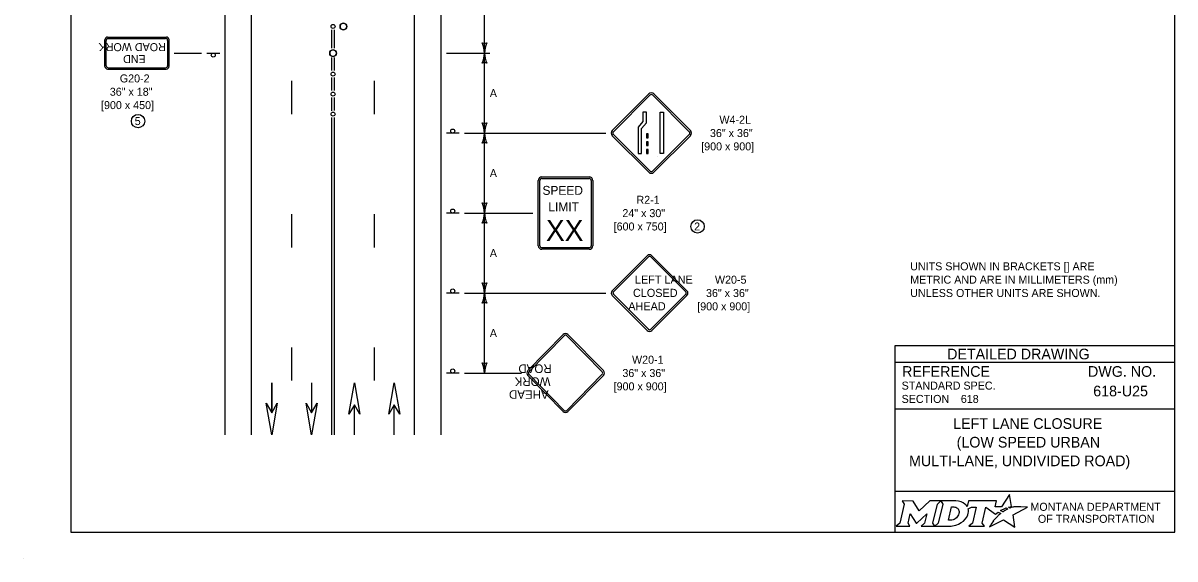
# Model space of a CAD drawing. Extents: x 49991.4 to 50021, y 49987.6 to 50011.4.
# Drawn here: x 49999.98 to 50008.61, y 49999.86 to 50003.88 of the extents above; entities that cross this region are included whole.
import ezdxf

# ---------------------------------------------------------------- set-up
doc = ezdxf.new("R2010")
doc.units = 0
for name, color, linetype in [('Level 1', 7, 'Continuous'), ('Level 2', 7, 'Continuous'), ('Level 25', 7, 'Continuous'), ('Level 3', 7, 'Continuous'), ('S_BOT_RW_TTL_Sheet_No_DF', 7, 'Continuous')]:
    doc.layers.add(name, color=color, linetype=linetype)

msp = doc.modelspace()

# ---------------------------------------------------------------- linework, layer by layer
at = {"layer": 'Level 1'}
for p, q in [((50001.4911, 50000.794), (50001.4911, 50008.6221)), ((50001.691, 50000.794), (50001.691, 50008.6221)), ((50002.911, 50000.794), (50002.911, 50008.6221)), ((50003.1109, 50000.794), (50003.1109, 50008.6221)), ((50002.291, 50003.6933), (50002.291, 50003.8311)), ((50002.311, 50003.6933), (50002.311, 50003.8311)), ((50000.5911, 50003.5573), (50000.5911, 50003.7573)), ((50000.6011, 50003.5623), (50000.6011, 50003.7523)), ((50000.6112, 50003.7773), (50001.0512, 50003.7773)), ((50000.6161, 50003.7673), (50001.0461, 50003.7673)), ((50001.0611, 50003.7523), (50001.0611, 50003.5623)), ((50001.0711, 50003.7573), (50001.0711, 50003.5573)), ((50001.3551, 50003.6573), (50001.4511, 50003.6573)), ((50002.291, 50003.5256), (50002.291, 50003.6233)), ((50002.311, 50003.5257), (50002.311, 50003.6233)), ((50000.6111, 50003.5373), (50001.0511, 50003.5373)), ((50000.6161, 50003.5473), (50001.0461, 50003.5473)), ((50001.9911, 50003.2), (50001.9911, 50003.45)), ((50002.291, 50003.3755), (50002.291, 50003.4732)), ((50002.311, 50003.3756), (50002.311, 50003.4732)), ((50002.6111, 50003.2), (50002.6111, 50003.45)), ((50002.291, 50003.2254), (50002.291, 50003.3231)), ((50002.311, 50003.2256), (50002.311, 50003.3231)), ((50002.291, 50000.794), (50002.291, 50003.1731)), ((50002.311, 50000.794), (50002.311, 50003.1731)), ((50003.2469, 50003.0573), (50003.1509, 50003.0573)), ((50003.8676, 50002.7292), (50004.2221, 50002.7292)), ((50003.8676, 50002.7168), (50004.2221, 50002.7168)), ((50003.8404, 50002.2125), (50003.8404, 50002.7021)), ((50003.8528, 50002.2125), (50003.8528, 50002.7021)), ((50004.2369, 50002.7021), (50004.2369, 50002.2125)), ((50004.2493, 50002.7021), (50004.2493, 50002.2125)), ((50001.9911, 50002.2), (50001.9911, 50002.45)), ((50002.6111, 50002.2), (50002.6111, 50002.45)), ((50003.2469, 50002.4573), (50003.1509, 50002.4573)), ((50004.2221, 50002.1977), (50003.8676, 50002.1977)), ((50004.2221, 50002.1853), (50003.8676, 50002.1853)), ((50004.6572, 50002.1376), (50004.3946, 50001.875)), ((50004.666, 50002.1289), (50004.4034, 50001.8662)), ((50004.9464, 50001.8662), (50004.6837, 50002.1289)), ((50004.9551, 50001.875), (50004.6926, 50002.1376)), ((50003.2469, 50001.8573), (50003.1509, 50001.8573)), ((50004.4034, 50001.8485), (50004.666, 50001.5858)), ((50004.6749, 50001.8573), (50004.6749, 50001.8573)), ((50004.6749, 50001.8573), (50004.6749, 50001.8573)), ((50004.6749, 50001.8573), (50004.6749, 50001.8573)), ((50004.6837, 50001.5858), (50004.9464, 50001.8485)), ((50004.3946, 50001.8397), (50004.6572, 50001.5771)), ((50004.6926, 50001.5771), (50004.9551, 50001.8397)), ((50003.7615, 50001.2754), (50004.0267, 50001.5461)), ((50003.7704, 50001.2667), (50004.0356, 50001.5374)), ((50004.0542, 50001.5374), (50004.3193, 50001.2667)), ((50004.063, 50001.5461), (50004.3282, 50001.2754)), ((50001.9911, 50001.2), (50001.9911, 50001.45)), ((50002.6111, 50001.2), (50002.6111, 50001.45)), ((50003.2469, 50001.2572), (50003.1509, 50001.2572)), ((50004.0267, 50000.9685), (50003.7615, 50001.2392)), ((50004.0356, 50000.9772), (50003.7704, 50001.2479)), ((50004.3193, 50001.2479), (50004.0542, 50000.9772)), ((50004.3282, 50001.2392), (50004.063, 50000.9685)), ((50001.8409, 50001.1841), (50001.8409, 50000.9582)), ((50001.8413, 50001.1841), (50001.8413, 50000.9582)), ((50002.1403, 50001.1841), (50002.1403, 50000.9582)), ((50002.1407, 50001.1841), (50002.1407, 50000.9582)), ((50002.4611, 50000.794), (50002.4611, 50001.0199)), ((50002.4613, 50000.794), (50002.4613, 50001.0199)), ((50002.7605, 50000.7939), (50002.7605, 50001.0198)), ((50002.7607, 50000.7939), (50002.7607, 50001.0198)), ((49999.9766, 49999.8624), (49999.9766, 49999.8624))]:
    msp.add_line(p, q, dxfattribs=at)
for points in [[(50008.6146, 50011.2628), (50000.3356, 50011.2628), (50000.3356, 50000.0624), (50008.6146, 50000.0624)], [(50002.4193, 50000.9476), (50002.4611, 50001.1841), (50002.5029, 50000.9476), (50002.4611, 50001.0198)], [(50002.7187, 50000.9475), (50002.7605, 50001.184), (50002.8023, 50000.9475), (50002.7605, 50001.0197)], [(50001.8829, 50001.0305), (50001.8413, 50000.794), (50001.7993, 50001.0305), (50001.8413, 50000.9583)], [(50002.1823, 50001.0305), (50002.1407, 50000.794), (50002.0987, 50001.0305), (50002.1407, 50000.9583)]]:
    msp.add_lwpolyline(points, close=True, dxfattribs=at)
for centre, radius in [((50002.301, 50003.8573), 0.015), ((50002.3785, 50003.8573), 0.025), ((50001.4031, 50003.6421), 0.0152), ((50002.301, 50003.6573), 0.025), ((50002.301, 50003.4994), 0.015), ((50002.301, 50003.3493), 0.015), ((50002.301, 50003.1993), 0.015), ((50003.1989, 50003.0725), 0.0152), ((50003.1989, 50002.4725), 0.0152), ((50003.1989, 50001.8725), 0.0152), ((50003.1989, 50001.2725), 0.0152)]:
    msp.add_circle(centre, radius, dxfattribs=at)
for centre, radius, start, end in [((50002.3785, 50003.8573), 0.025, 360, 180), ((50002.3785, 50003.8573), 0.025, 180, 0), ((50000.6112, 50003.7573), 0.02, 90, 180), ((50000.6161, 50003.7523), 0.015, 90, 180), ((50001.0461, 50003.7523), 0.015, 360, 90), ((50001.0512, 50003.7573), 0.02, 360, 90), ((50002.301, 50003.6573), 0.025, 360, 180), ((50002.301, 50003.6573), 0.025, 180, 0), ((50000.6111, 50003.5573), 0.02, 180, 270), ((50000.6161, 50003.5623), 0.015, 180, 270), ((50001.0461, 50003.5623), 0.015, 270, 360), ((50001.0511, 50003.5573), 0.02, 270, 360), ((50003.8676, 50002.7021), 0.0272, 90, 180), ((50003.8676, 50002.7021), 0.0148, 90, 180), ((50004.2221, 50002.7021), 0.0272, 0, 90), ((50004.2221, 50002.7021), 0.0148, 0, 90), ((50003.8676, 50002.2125), 0.0272, 180, 270), ((50003.8676, 50002.2125), 0.0148, 180, 270), ((50004.2221, 50002.2125), 0.0148, 270, 360), ((50004.2221, 50002.2125), 0.0272, 270, 360), ((50004.6749, 50002.1199), 0.025, 45, 135), ((50004.6749, 50002.12), 0.0125, 45.00005, 135.00016), ((50004.4123, 50001.8573), 0.025, 135, 225), ((50004.4122, 50001.8573), 0.0125, 135.00016, 224.99995), ((50004.9376, 50001.8573), 0.0125, 314.99984, 45.00005), ((50004.9375, 50001.8573), 0.025, 315, 45), ((50004.6749, 50001.5947), 0.0125, 224.99995, 314.99984), ((50004.6749, 50001.5947), 0.025, 225, 315)]:
    msp.add_arc(centre, radius, start, end, dxfattribs=at)
for centre, major_axis, ratio, start_param, end_param in [((50004.0449, 50001.5279), (0, 0.0258), 0.98963, 5.497787, 7.068583), ((50004.0449, 50001.5279), (0, 0.0134), 0.98, 5.497787, 7.068583), ((50003.7796, 50001.2572), (0, 0.0258), 0.98963, 0.785394, 2.356194), ((50003.7796, 50001.2572), (0, 0.0134), 0.98, 0.785394, 2.356194), ((50004.3101, 50001.2572), (0, 0.0134), 0.98, 3.926991, 5.497787), ((50004.3101, 50001.2572), (0, 0.0258), 0.98963, 3.926991, 5.497787), ((50004.0449, 50000.9866), (0, -0.0134), 0.98, 5.497795, 7.068583), ((50004.0449, 50000.9866), (0, -0.0258), 0.98963, 5.497795, 7.068583)]:
    msp.add_ellipse(centre, major_axis=major_axis, ratio=ratio, start_param=start_param, end_param=end_param, dxfattribs=at)
at = {"layer": 'Level 2'}
for p, q in [((50008.6146, 50001.4624), (50006.5146, 50001.4624)), ((50006.5146, 50001.4624), (50006.5146, 50000.0624)), ((50008.6146, 50001.3374), (50006.5146, 50001.3374)), ((50008.2507, 50001.1223), (50008.2507, 50001.1223)), ((50008.6146, 50000.9874), (50006.5146, 50000.9874)), ((50007.0089, 50001.0629), (50007.0089, 50001.0629)), ((50007.5646, 50000.7383), (50007.5646, 50000.7383)), ((50008.6146, 50000.3693), (50006.5146, 50000.3693))]:
    msp.add_line(p, q, dxfattribs=at)
for points in [[(50006.5701, 50000.2974), (50006.5842, 50000.274), (50006.5507, 50000.1307), (50006.525, 50000.1082), (50006.6266, 50000.1082), (50006.6131, 50000.131), (50006.6293, 50000.2011), (50006.673, 50000.1321), (50006.6783, 50000.1321), (50006.7534, 50000.2016), (50006.737, 50000.1305), (50006.7123, 50000.1085), (50006.8139, 50000.1085), (50006.8001, 50000.1318), (50006.8333, 50000.2742)], [(50006.8333, 50000.2742), (50006.8586, 50000.2974), (50006.7762, 50000.2974), (50006.6966, 50000.2244), (50006.6521, 50000.2971), (50006.5701, 50000.2974)], [(50006.9722, 50000.2974), (50006.8586, 50000.2974), (50006.8733, 50000.2745), (50006.8394, 50000.1307), (50006.8139, 50000.1085), (50006.9245, 50000.1085)], [(50007.3771, 50000.2447), (50007.3668, 50000.2503), (50007.3784, 50000.2531), (50007.39, 50000.2551), (50007.3726, 50000.3452), (50007.3131, 50000.2539), (50007.2658, 50000.2532), (50007.2761, 50000.2973), (50007.0669, 50000.2974), (50007.0568, 50000.2549), (50007.051, 50000.2632)], [(50006.9962, 50000.2107), (50006.995, 50000.2026), (50006.9918, 50000.1933), (50006.9876, 50000.1851), (50006.982, 50000.1776), (50006.9755, 50000.1707), (50006.9676, 50000.1644), (50006.9593, 50000.1597), (50006.9502, 50000.1558), (50006.9411, 50000.1535), (50006.9319, 50000.1526), (50006.916, 50000.1526), (50006.9396, 50000.2526), (50006.9556, 50000.2526), (50006.9632, 50000.252), (50006.9708, 50000.2501), (50006.9774, 50000.2471), (50006.9835, 50000.2429), (50006.9883, 50000.2379), (50006.992, 50000.2319), (50006.9947, 50000.2257), (50006.9963, 50000.2183), (50006.9963, 50000.2153), (50006.9962, 50000.2107)], [(50007.0636, 50000.2383), (50007.0882, 50000.2514), (50007.1251, 50000.2514), (50007.0965, 50000.1309), (50007.069, 50000.1082), (50007.1852, 50000.1082), (50007.1682, 50000.1311), (50007.1964, 50000.2513), (50007.2677, 50000.1996), (50007.2888, 50000.2147), (50007.3085, 50000.2038)], [(50007.2527, 50000.1479), (50007.2374, 50000.1235), (50007.2327, 50000.116), (50007.2269, 50000.1074), (50007.2246, 50000.1031), (50007.3299, 50000.1562), (50007.4138, 50000.1011), (50007.4007, 50000.1938), (50007.5076, 50000.2522), (50007.4583, 50000.253), (50007.4282, 50000.2534), (50007.4074, 50000.2537), (50007.4006, 50000.2522), (50007.3957, 50000.251), (50007.3873, 50000.2487), (50007.3771, 50000.2447)], [(50007.3267, 50000.2171), (50007.3243, 50000.2154), (50007.306, 50000.225), (50007.3163, 50000.2307), (50007.3204, 50000.2329), (50007.329, 50000.2369), (50007.3347, 50000.2395), (50007.3426, 50000.2425), (50007.3499, 50000.2452), (50007.3617, 50000.2378), (50007.3577, 50000.2357), (50007.3531, 50000.2332), (50007.3489, 50000.231), (50007.3439, 50000.2281), (50007.342, 50000.227), (50007.3393, 50000.2254), (50007.3368, 50000.224), (50007.3345, 50000.2224), (50007.3319, 50000.2206), (50007.3292, 50000.2188), (50007.3267, 50000.2171)], [(50006.9702, 50000.1158), (50006.9786, 50000.1184), (50006.9916, 50000.1238), (50007.012, 50000.1348)], [(50007.2666, 50000.164), (50007.2666, 50000.164)]]:
    msp.add_lwpolyline(points, dxfattribs=at)
for centre in [(50000.839, 50003.1473), (50005.0344, 50002.3567)]:
    msp.add_circle(centre, 0.0501, dxfattribs=at)
for centre, radius, start, end in [((50006.9953, 50000.219), 0.0709, 339.53292, 15.85821), ((50006.9513, 50000.2363), 0.1183, 300.91025, 339.13831)]:
    msp.add_arc(centre, radius, start, end, dxfattribs=at)
for centre, major_axis, ratio, start_param, end_param in [((50006.9701, 50000.25), (0.0834, -0.0037), 0.568097, 0.61298, 1.570796), ((50007.0257, 50000.2573), (0.0361, -0.0295), 0.469099, 1.225588, 1.570796), ((50007.2974, 50000.1941), (-0.0112, -0.0097), 0.021651, 3.157348, 6.283185), ((50006.9248, 50000.2568), (0, 0.1484), 0.987302, 3.139398, 3.456847), ((50007.2597, 50000.1559), (-0.00694, -0.00806), 0.008222, 0, 3.137361), ((50007.2764, 50000.1742), (-0.0098, -0.0102), 0.016458, 3.141593, 6.279097)]:
    msp.add_ellipse(centre, major_axis=major_axis, ratio=ratio, start_param=start_param, end_param=end_param, dxfattribs=at)
at = {"layer": 'Level 25'}
for p, q in [((50004.6684, 50003.3513), (50004.3941, 50003.077)), ((50004.4034, 50003.0678), (50004.6776, 50003.342)), ((50004.6983, 50003.342), (50004.9725, 50003.0678)), ((50004.6983, 50003.342), (50004.6983, 50003.342)), ((50004.9818, 50003.077), (50004.7075, 50003.3513)), ((50004.7543, 50002.9044), (50004.7543, 50003.2137)), ((50004.7543, 50003.2137), (50004.7799, 50003.2137)), ((50004.7799, 50003.2137), (50004.7799, 50002.9044)), ((50004.3941, 50003.0379), (50004.6684, 50002.7636)), ((50004.6776, 50002.7729), (50004.4034, 50003.0471)), ((50004.9725, 50003.0471), (50004.6983, 50002.7729)), ((50004.7075, 50002.7636), (50004.9818, 50003.0379)), ((50004.7799, 50002.9044), (50004.7543, 50002.9044))]:
    msp.add_line(p, q, dxfattribs=at)
msp.add_lwpolyline([(50004.7374, 50002.8851), (50004.7372, 50002.8853)], dxfattribs=at)
for centre, radius, start, end in [((50004.6879, 50003.3317), 0.0277, 45.00007, 134.99993), ((50004.6879, 50003.3317), 0.0146, 45.00007, 134.99993), ((50004.4137, 50003.0575), 0.0277, 134.99992, 225.00007), ((50004.4137, 50003.0575), 0.0146, 134.99993, 225.00007), ((50004.9622, 50003.0575), 0.0146, 314.99992, 45.00007), ((50004.9622, 50003.0575), 0.0277, 314.99992, 45.00007), ((50004.6879, 50002.7832), 0.0277, 225.00007, 314.99993), ((50004.6879, 50002.7832), 0.0146, 225.00007, 314.99993)]:
    msp.add_arc(centre, radius, start, end, dxfattribs=at)
at = {"layer": 'Level 3'}
for p, q in [((50003.4369, 50003.6573), (50003.4369, 50004.4573)), ((50001.1111, 50003.6573), (50001.3151, 50003.6573)), ((50003.1509, 50003.6573), (50003.4769, 50003.6573)), ((50003.4369, 50003.0573), (50003.4369, 50003.6573)), ((50003.2869, 50003.0573), (50004.346, 50003.0573)), ((50003.4369, 50002.4573), (50003.4369, 50003.0573)), ((50003.2869, 50002.4573), (50003.8004, 50002.4573)), ((50003.4369, 50001.8573), (50003.4369, 50002.4573)), ((50003.2869, 50001.8573), (50004.3473, 50001.8573)), ((50003.4369, 50001.2572), (50003.4369, 50001.8572)), ((50003.2869, 50001.2572), (50003.7141, 50001.2572))]:
    msp.add_line(p, q, dxfattribs=at)
for centre, radius, start, end in [((50003.4369, 50003.7855), 0.0548, 252.13882, 287.86118), ((50003.2042, 50003.6458), 0.233, 2.82731, 22.07716), ((50003.2147, 50003.6665), 0.2223, 337.45601, 357.63952), ((50003.659, 50003.6481), 0.2223, 157.45601, 177.63952), ((50003.6696, 50003.6688), 0.233, 182.82731, 202.07716), ((50003.4369, 50003.5291), 0.0548, 72.13882, 107.86118), ((50003.4369, 50003.1855), 0.0548, 252.13882, 287.86118), ((50003.2042, 50003.0458), 0.233, 2.82731, 22.07716), ((50003.2147, 50003.0664), 0.2223, 337.45601, 357.63952), ((50003.659, 50003.0481), 0.2223, 157.45601, 177.63952), ((50003.6696, 50003.0688), 0.233, 182.82731, 202.07716), ((50003.4369, 50002.9291), 0.0548, 72.13882, 107.86118), ((50003.4369, 50002.5855), 0.0548, 252.13882, 287.86118), ((50003.2042, 50002.4458), 0.233, 2.82731, 22.07716), ((50003.659, 50002.4481), 0.2223, 157.45601, 177.63952), ((50003.2147, 50002.4664), 0.2223, 337.45601, 357.63952), ((50003.6696, 50002.4688), 0.233, 182.82731, 202.07716), ((50003.4369, 50002.3291), 0.0548, 72.13882, 107.86118), ((50003.4369, 50001.9855), 0.0548, 252.13882, 287.86118), ((50003.2042, 50001.8458), 0.233, 2.82731, 22.07716), ((50003.659, 50001.8481), 0.2223, 157.45601, 177.63952), ((50003.2147, 50001.8664), 0.2223, 337.45601, 357.63952), ((50003.6696, 50001.8687), 0.233, 182.82731, 202.07716), ((50003.4369, 50001.729), 0.0548, 72.13882, 107.86118), ((50003.4369, 50001.3855), 0.0548, 252.13882, 287.86118), ((50003.2042, 50001.2457), 0.233, 2.82731, 22.07716), ((50003.659, 50001.2481), 0.2223, 157.45601, 177.63952)]:
    msp.add_arc(centre, radius, start, end, dxfattribs=at)
at = {"layer": 'S_BOT_RW_TTL_Sheet_No_DF'}
for p, q in [((50004.6253, 50003.1432), (50004.5886, 50003.1006)), ((50004.6509, 50003.2137), (50004.6253, 50003.2137)), ((50004.6253, 50003.2137), (50004.6253, 50003.1432)), ((50004.6509, 50003.1337), (50004.6509, 50003.2137)), ((50004.5886, 50003.1006), (50004.5886, 50002.9044)), ((50004.6143, 50003.0911), (50004.6509, 50003.1337)), ((50004.6143, 50002.9044), (50004.6143, 50003.0911)), ((50004.6643, 50003.0512), (50004.6507, 50003.0512)), ((50004.6507, 50003.0512), (50004.6507, 50003.0218)), ((50004.6643, 50003.0218), (50004.6643, 50003.0512)), ((50004.6507, 50003.0218), (50004.6643, 50003.0218)), ((50004.6643, 50002.9925), (50004.6507, 50002.9925)), ((50004.6507, 50002.9925), (50004.6507, 50002.9631)), ((50004.6643, 50002.9631), (50004.6643, 50002.9925)), ((50004.5886, 50002.9044), (50004.6143, 50002.9044)), ((50004.6507, 50002.9631), (50004.6643, 50002.9631)), ((50004.6647, 50002.9337), (50004.6511, 50002.9337)), ((50004.6511, 50002.9337), (50004.6511, 50002.9044)), ((50004.6511, 50002.9044), (50004.6647, 50002.9044)), ((50004.6647, 50002.9044), (50004.6647, 50002.9337))]:
    msp.add_line(p, q, dxfattribs=at)

# ---------------------------------------------------------------- texts
at = {"layer": 'Level 1'}
for s, height, p in [('ROAD WORK', 0.06, (50001.0469, 50003.7319)), ('END', 0.06, (50000.8963, 50003.6419)), ('ROAD', 0.06453, (50003.9407, 50001.3218)), ('WORK', 0.06453, (50003.9316, 50001.225)), ('AHEAD', 0.06453, (50003.9179, 50001.1283))]:
    msp.add_text(s, height=height, rotation=180, dxfattribs=at).set_placement(p)
for s, height, p in [('SPEED', 0.06696, (50003.8717, 50002.5941)), ('LIMIT', 0.06696, (50003.9161, 50002.4703)), ('XX', 0.15775, (50003.8977, 50002.2483)), ('LEFT LANE', 0.06086, (50004.5649, 50001.9275)), ('CLOSED', 0.06086, (50004.5501, 50001.8281)), ('  AHEAD', 0.06086, (50004.47, 50001.7277))]:
    msp.add_text(s, height=height, dxfattribs=at).set_placement(p)
at = {"layer": 'Level 2'}
for s, height, p in [('G20-2', 0.06, (50000.7024, 50003.4373)), ('36" x 18"', 0.06, (50000.6272, 50003.3373)), ('[900 x 450]', 0.06, (50000.5616, 50003.2373)), ('5', 0.06, (50000.8141, 50003.1173)), ('W4-2L', 0.06, (50005.1985, 50003.1275)), ('36" x 36"', 0.06, (50005.1277, 50003.0275)), ('[900 x 900]', 0.06, (50005.0621, 50002.9275)), ('R2-1', 0.06, (50004.5766, 50002.5267)), ('24" x 30"', 0.06, (50004.471, 50002.4267)), ('[600 x 750]', 0.06, (50004.4055, 50002.3267)), ('2', 0.06, (50005.0092, 50002.3267)), ('UNITS SHOWN IN BRACKETS [] ARE ', 0.06, (50006.6294, 50002.0278)), ('W20-5', 0.06, (50005.165, 50001.9274)), ('METRIC AND ARE IN MILLIMETERS (mm) ', 0.06, (50006.6294, 50001.9278)), ('36" x 36"', 0.06, (50005.0979, 50001.8274)), ('UNLESS OTHER UNITS ARE SHOWN.', 0.06, (50006.6294, 50001.8278)), ('[900 x 900]', 0.06, (50005.0323, 50001.7274)), ('DETAILED DRAWING', 0.0799, (50006.9063, 50001.3599)), ('W20-1', 0.06, (50004.5433, 50001.3272)), ('36" x 36"', 0.06, (50004.471, 50001.2272)), ('REFERENCE', 0.08, (50006.5682, 50001.229)), ('DWG. NO.', 0.08, (50007.9624, 50001.229)), ('[900 x 900]', 0.06, (50004.4055, 50001.1272)), ('STANDARD SPEC.', 0.06, (50006.5649, 50001.133)), ('618-U25', 0.08, (50008.0018, 50001.0823)), ('SECTION', 0.06, (50006.5649, 50001.033)), ('MONTANA DEPARTMENT', 0.06, (50007.5308, 50000.2236)), ('OF TRANSPORTATION', 0.06, (50007.587, 50000.1336))]:
    msp.add_text(s, height=height, dxfattribs=at).set_placement(p)
for p in [(50003.4769, 50003.3273), (50003.4769, 50002.7273), (50003.4769, 50002.1273), (50003.4769, 50001.5272)]:
    msp.add_text('A', height=0.06, rotation=360, dxfattribs=at).set_placement(p)
at = {"layer": 'Level 3'}
for s, height, p in [('618', 0.06, (50007.0089, 50001.0329)), ('LEFT LANE CLOSURE', 0.08, (50006.9515, 50000.8383)), ('(LOW SPEED URBAN', 0.08, (50006.9775, 50000.6983)), ('MULTI-LANE, UNDIVIDED ROAD)', 0.08, (50006.6207, 50000.5583))]:
    msp.add_text(s, height=height, dxfattribs=at).set_placement(p)

doc.saveas('drawing.dxf')
